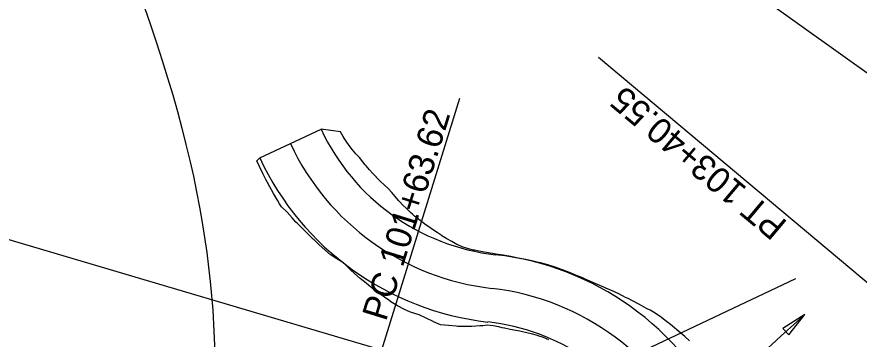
# Model space of a CAD drawing. Extents: x 1 to 1477871, y 1 to 1872901.
# Drawn here: x 1443824.9 to 1444023.8, y 1855031.6 to 1855107.8 of the extents above; entities that cross this region are included whole.
import ezdxf

# ---------------------------------------------------------------- set-up
doc = ezdxf.new("R2010")
doc.units = 0
for name, color, linetype in [('R_Drive', 7, 'Continuous'), ('R_Floodplain', 7, 'Continuous'), ('R_Horz Alg Annot', 7, 'Continuous'), ('R_No Plot', 7, 'Continuous'), ('R_Proposed Const Limits_Cut', 7, 'Continuous'), ('R_Proposed Const Limits_Fill', 7, 'Continuous'), ('R_ROW', 7, 'Continuous'), ('R_Temp Easement', 7, 'Continuous'), ('R_Water', 7, 'Continuous')]:
    doc.layers.add(name, color=color, linetype=linetype)

msp = doc.modelspace()

# ---------------------------------------------------------------- linework, layer by layer
at = {"layer": 'R_Drive'}
msp.add_line((1443882.25, 1855074.41), (1443896.75, 1855081.18), dxfattribs=at)
for centre, radius, start, end in [((1443943.86, 1855103.19), 52, 205.0438, 263.4809), ((1443943.86, 1855103.19), 68, 205.0438, 263.4809), ((1443930.24, 1854983.97), 68, 25.3079, 83.4809), ((1443930.24, 1854983.97), 52, 29.5544, 83.4809)]:
    msp.add_arc(centre, radius, start, end, dxfattribs=at)
at = {"layer": 'R_Floodplain'}
msp.add_open_spline([(1444534.23, 1857777.84), (1444398.78, 1857609.12), (1444367.89, 1857131.47), (1444306.1, 1856808.28), (1444134.95, 1856378.26), (1444024.62, 1856227.92), (1443837.91, 1855964.82), (1443664.53, 1855852.06), (1443479.03, 1855867.82), (1443335.96, 1855886.01), (1443298.37, 1855854.49), (1443356.57, 1855756.28), (1443606.51, 1855482.27), (1443757.19, 1855307.33), (1443863.11, 1855113.58), (1443878.59, 1855007.91), (1443849.87, 1854910.07), (1443760.66, 1854753.08), (1443429.28, 1854512.04), (1443240.87, 1854371.16), (1443115.26, 1854254.04), (1443060.94, 1853889.1), (1443099.99, 1853680.31), (1443032.09, 1853386.66), (1443001.54, 1853198.25), (1444534.23, 1857777.84), (1443001.54, 1853198.25)], degree=3, dxfattribs=at)
at = {"layer": 'R_Horz Alg Annot'}
for points in [[(1444054.15, 1855021.02), (1443962.22, 1855098.16)], [(1443893.97, 1854973.93), (1443929.52, 1855088.55)]]:
    msp.add_lwpolyline(points, dxfattribs=at)
at = {"layer": 'R_No Plot'}
for centre, start, end in [((1443943.86, 1855103.19), 205.0438, 263.4809), ((1443930.24, 1854983.97), 22.959, 83.4809)]:
    msp.add_arc(centre, 60, start, end, dxfattribs=at)
at = {"layer": 'R_Proposed Const Limits_Cut'}
for points in [[(1443943.28, 1855050.72), (1443942.53, 1855050.88), (1443941.52, 1855051.09), (1443939.75, 1855051.41), (1443937.98, 1855051.69), (1443937.18, 1855051.8), (1443936.63, 1855051.89), (1443935.3, 1855052.13), (1443933.97, 1855052.37), (1443932.94, 1855052.58), (1443932.64, 1855052.65), (1443931.33, 1855052.99), (1443930.04, 1855053.37), (1443928.85, 1855053.97), (1443928.81, 1855053.99), (1443927.61, 1855054.64), (1443926.43, 1855055.32), (1443925.28, 1855056.03), (1443925.11, 1855056.14), (1443924.15, 1855056.77), (1443923.04, 1855057.51), (1443921.95, 1855058.26), (1443921.58, 1855058.52), (1443920.88, 1855059.04), (1443919.84, 1855059.84), (1443918.82, 1855060.67), (1443918.3, 1855061.12), (1443917.84, 1855061.54), (1443916.89, 1855062.43), (1443915.98, 1855063.36), (1443915.35, 1855064.03), (1443915.1, 1855064.31), (1443914.25, 1855065.27), (1443913.42, 1855066.25), (1443912.68, 1855067.1), (1443912.58, 1855067.19), (1443911.65, 1855068.02), (1443910.75, 1855068.87), (1443909.86, 1855069.76), (1443909.79, 1855069.83), (1443909.01, 1855070.66), (1443908.18, 1855071.59), (1443907.37, 1855072.54), (1443907.16, 1855072.81), (1443906.6, 1855073.52), (1443905.8, 1855074.48), (1443904.95, 1855075.4), (1443904.57, 1855075.83), (1443904.13, 1855076.36), (1443903.37, 1855077.36), (1443902.65, 1855078.39), (1443902.21, 1855079.07), (1443901.98, 1855079.46), (1443901.36, 1855080.55), (1443896.75, 1855081.18)], [(1443902, 1855049.59), (1443900.47, 1855050.53), (1443899.12, 1855051.41), (1443898.98, 1855051.53), (1443897.62, 1855052.7), (1443896.3, 1855053.91), (1443895.01, 1855055.15), (1443894.91, 1855055.25), (1443893.71, 1855056.38), (1443892.4, 1855057.62), (1443891.14, 1855058.91), (1443890.8, 1855059.26), (1443889.91, 1855060.24), (1443888.72, 1855061.6), (1443887.41, 1855062.87), (1443886.96, 1855063.57), (1443886.45, 1855064.42), (1443885.53, 1855065.98), (1443884.64, 1855067.55), (1443884.09, 1855068.58), (1443883.78, 1855069.15), (1443882.96, 1855070.75), (1443882.18, 1855072.38), (1443881.55, 1855073.74), (1443882.25, 1855074.41)]]:
    msp.add_lwpolyline(points, dxfattribs=at)
at = {"layer": 'R_Proposed Const Limits_Fill'}
for points in [[(1443950.52, 1855031.38), (1443949.29, 1855031.97), (1443947.99, 1855032.39), (1443947.84, 1855032.44), (1443946.67, 1855032.74), (1443945.35, 1855033.05), (1443944.02, 1855033.35), (1443943.66, 1855033.43), (1443942.69, 1855033.62), (1443941.36, 1855033.85), (1443940.04, 1855034.15), (1443939.48, 1855034.29), (1443938.73, 1855034.47), (1443937.4, 1855034.76), (1443936.05, 1855034.85), (1443934.97, 1855034.75), (1443934.21, 1855034.69), (1443932.36, 1855034.6), (1443930.5, 1855034.57), (1443929.06, 1855034.6), (1443928.64, 1855034.62), (1443926.79, 1855034.79), (1443924.93, 1855034.98), (1443923.28, 1855035.69), (1443923.22, 1855035.72), (1443921.54, 1855036.5), (1443919.88, 1855037.32), (1443918.12, 1855037.86), (1443917.85, 1855037.93), (1443916.42, 1855038.55), (1443914.81, 1855039.44), (1443913.25, 1855040.43), (1443912.74, 1855040.77), (1443911.74, 1855041.47), (1443910.25, 1855042.55), (1443908.8, 1855043.65), (1443908.05, 1855044.24), (1443907.38, 1855044.79), (1443905.98, 1855045.94), (1443904.62, 1855047.13), (1443903.68, 1855047.99), (1443903.29, 1855048.34), (1443902, 1855049.59)], [(1443983.75, 1855031.14), (1443982.61, 1855032.17), (1443981.18, 1855033.4), (1443979.73, 1855034.61), (1443979.24, 1855035.01), (1443978.27, 1855035.78), (1443976.78, 1855036.91), (1443975.24, 1855037.97), (1443974.42, 1855038.41), (1443973.58, 1855038.86), (1443971.94, 1855039.76), (1443970.29, 1855040.61), (1443969.22, 1855041.15), (1443968.64, 1855041.44), (1443967.01, 1855042.27), (1443965.35, 1855043.04), (1443964, 1855043.62), (1443963.67, 1855043.75), (1443962, 1855044.47), (1443960.37, 1855045.23), (1443958.78, 1855045.93), (1443958.72, 1855045.96), (1443957.05, 1855046.64), (1443955.39, 1855047.33), (1443953.71, 1855047.99), (1443953.51, 1855048.06), (1443952.02, 1855048.6), (1443950.3, 1855049.13), (1443948.56, 1855049.59), (1443948.08, 1855049.71), (1443946.81, 1855050.01), (1443945.05, 1855050.37), (1443943.28, 1855050.72)]]:
    msp.add_lwpolyline(points, dxfattribs=at)
at = {"layer": 'R_ROW'}
for p, q in [((1443565.8, 1855131.35), (1443949.34, 1855017.73)), ((1443949.34, 1855017.73), (1444008.81, 1855045.93))]:
    msp.add_line(p, q, dxfattribs=at)
at = {"layer": 'R_Temp Easement'}
msp.add_line((1443988.19, 1855121.34), (1444040.86, 1855083.67), dxfattribs=at)
at = {"layer": 'R_Water'}
for p, q in [((1444010.93, 1855037.38), (1444005.77, 1855034.13)), ((1444007.19, 1855032.56), (1444010.93, 1855037.38)), ((1444005.77, 1855034.13), (1444007.19, 1855032.56))]:
    msp.add_line(p, q, dxfattribs=at)
msp.add_lwpolyline([(1443999.82, 1855027.3), (1444001.68, 1855028.99), (1444003.08, 1855030.26), (1444005.37, 1855032.34), (1444009.06, 1855035.69), (1444010.93, 1855037.38)], dxfattribs=at)

# ---------------------------------------------------------------- texts
at = {"layer": 'R_Horz Alg Annot'}
for s, rotation, p in [('PT 103+40.55', 140, (1444007.11, 1855059.19)), ('PC 101+63.62', 72.7667, (1443912.05, 1855035.6))]:
    msp.add_text(s, height=6, rotation=rotation, dxfattribs=at).set_placement(p)

doc.saveas('drawing.dxf')
